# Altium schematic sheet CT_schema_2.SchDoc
size 403 x 258 mm
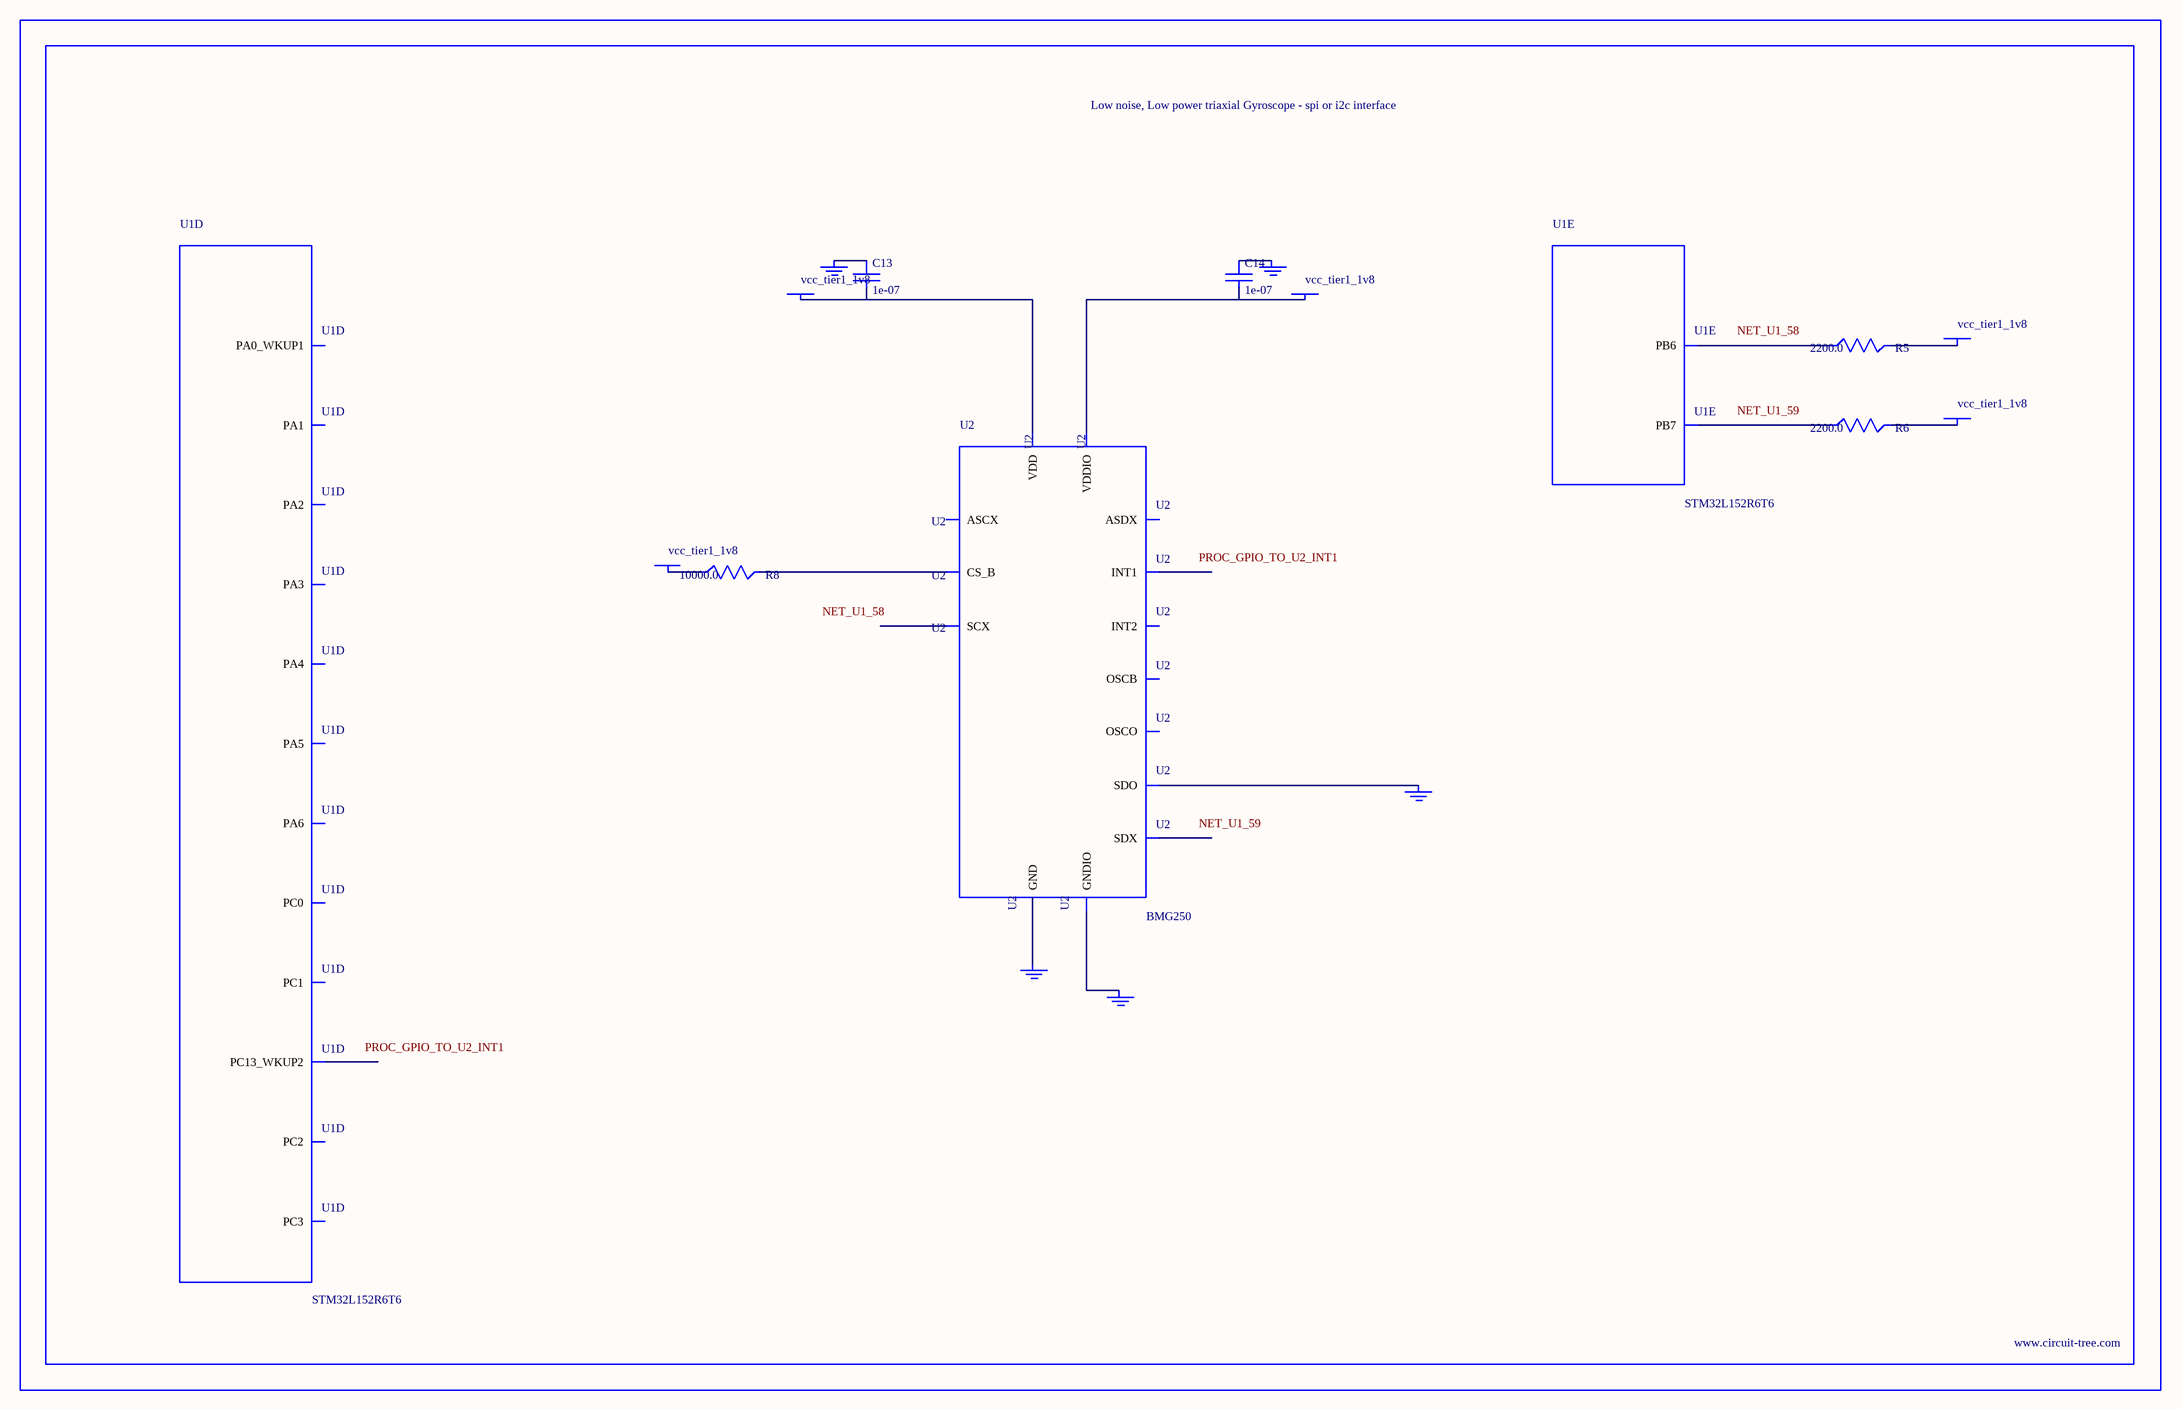
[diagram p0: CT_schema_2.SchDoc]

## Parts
BORDER1  (no value)
C13  1e-07  [C0402]
C14  1e-07  [C0402]
GND_INSTANCE_1_0  (no value)
GND_INSTANCE_1_1  (no value)
GND_INSTANCE_1_2  (no value)
GND_INSTANCE_1_3  (no value)
GND_INSTANCE_1_4  (no value)
POWER_INSTANCE_1_0  vcc_tier1_1v8
POWER_INSTANCE_1_1  vcc_tier1_1v8
POWER_INSTANCE_1_2  vcc_tier1_1v8
POWER_INSTANCE_1_3  vcc_tier1_1v8
POWER_INSTANCE_1_4  vcc_tier1_1v8
R5  2200.0  [R0603]
R6  2200.0  [R0603]
R8  10000.0  [R0603]
U1  STM32L152R6T6  [LQFP64]  (parts D,E of 7)
U2  BMG250  [LGA-14]

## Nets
NetC13_1: C13.1 GND_INSTANCE_1_3.0(GND)
NetC13_2: C13.2 POWER_INSTANCE_1_1.0(PWR) U2.8(VDD)
NetC14_1: C14.1 GND_INSTANCE_1_1.0(GND)
NetC14_2: C14.2 POWER_INSTANCE_1_0.0(PWR) U2.5(VDDIO)
NetGND_INSTANCE_1_0_0: GND_INSTANCE_1_0.0(GND) U2.1(SDO)
NetGND_INSTANCE_1_2_0: GND_INSTANCE_1_2.0(GND) U2.6(GNDIO)
NetGND_INSTANCE_1_4_0: GND_INSTANCE_1_4.0(GND) U2.7(GND)
NetPOWER_INSTANCE_1_2_0: POWER_INSTANCE_1_2.0(PWR) R8.1
NetPOWER_INSTANCE_1_3_0: POWER_INSTANCE_1_3.0(PWR) R5.2
NetPOWER_INSTANCE_1_4_0: POWER_INSTANCE_1_4.0(PWR) R6.2
NetR5_1: R5.1 U1.58(PB6)
NetR6_1: R6.1 U1.59(PB7)
NetR8_2: R8.2 U2.12(CS_B)

Not connected (* = marked no-connect by the designer): U1 2(PC13_WKUP2) 8(PC0) 9(PC1) 10(PC2) 11(PC3) 14(PA0_WKUP1) 15(PA1) 16(PA2) 17(PA3) 20(PA4) 21(PA5) 22(PA6); U2 2(ASDX) 3(ASCX) 4(INT1) 9(INT2) 10(OSCB) 11(OSCO) 13(SCX) 14(SDX)

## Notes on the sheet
- Labels drawn without touching a wire or pin: NET_U1_58, NET_U1_59, PROC_GPIO_TO_U2_INT1

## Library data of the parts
BORDER1 = BORDER_PAGE1
C13 C14 = C0402C104K3RACTU
GND_INSTANCE_1_0-GND_INSTANCE_1_4 = GND
POWER_INSTANCE_1_0-POWER_INSTANCE_1_4 = PWR
R5 R6 = RC0603JR-072K2L
R8 = RC0603JR-0710KL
